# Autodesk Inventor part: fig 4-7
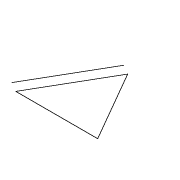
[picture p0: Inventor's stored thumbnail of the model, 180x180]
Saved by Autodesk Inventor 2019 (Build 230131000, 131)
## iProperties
Created: 2005-02
Part Number: fig 4-7
Document SubType Name: Modeling
Designer: CADCIM
Manufacturer: Standard
Standards Organization: Custom
Density: 1 g/cm^3
Material: Generic
Appearance: Default
Author: CADCIM
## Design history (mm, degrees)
sketch "Sketch1"
  geometry: L1 (-3.883, 28.419)-(-24.946, -8.063); L2 (-24.946, -8.063)-(17.18, -8.063); L3 (17.18, -8.063)-(-3.883, 28.419); L4 (-8.847, 31.285)-(-29.909, -5.197)
  constraints: 8 end point, 2 equal length, 1 horizontal, 1 parallel, 1 other
